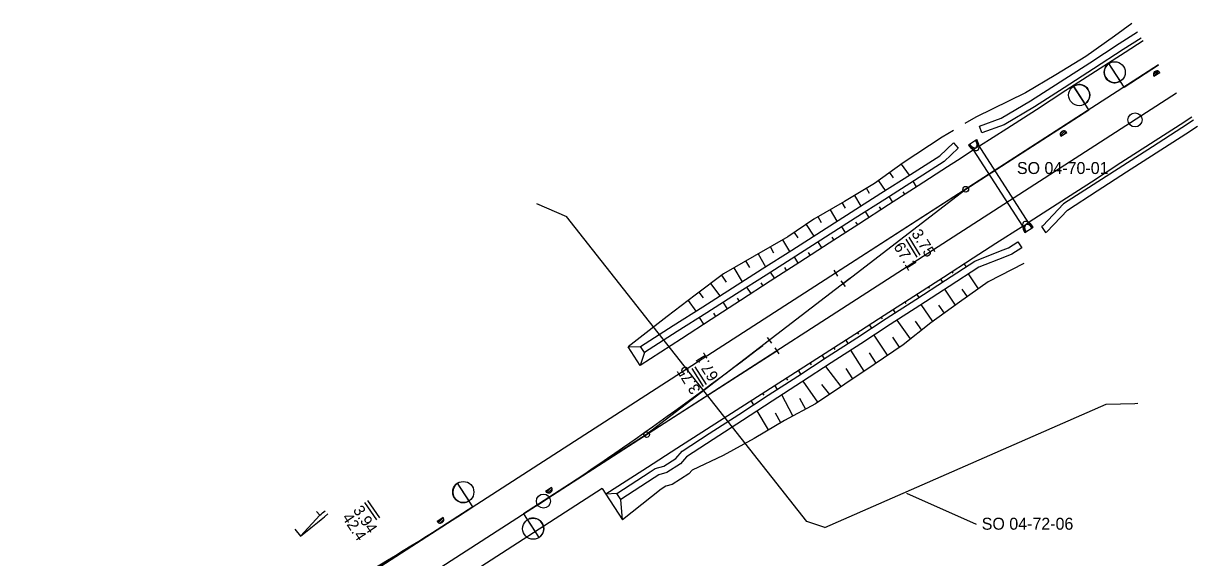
# Model space of a CAD drawing. Extents: x -723225 to -722352, y -1040354 to -1039760.
# Drawn here: x -722561.5 to -722394.6, y -1039969.1 to -1039893.3 of the extents above; entities that cross this region are included whole.
import ezdxf

# ---------------------------------------------------------------- set-up
doc = ezdxf.new("R2010")
doc.units = 0
for name, color, linetype in [('_PS_SO_číslo', 7, 'Continuous'), ('SO 03_01_01', 7, 'Continuous'), ('SO 04_70_01', 7, 'Continuous'), ('SO 04_72_06', 7, 'Continuous')]:
    doc.layers.add(name, color=color, linetype=linetype)

msp = doc.modelspace()

# ---------------------------------------------------------------- linework, layer by layer
at = {"layer": '_PS_SO_číslo'}
msp.add_line((-722435.98, -1039960.01), (-722426.1, -1039964.39), dxfattribs=at)
at = {"layer": 'SO 03_01_01'}
for p, q in [((-722400.19, -1039899.16), (-722541.14, -1039990)), ((-722400.91, -1039900.51), (-722400.39, -1039899.99)), ((-722400.85, -1039900.73), (-722400.17, -1039900.05)), ((-722400.17, -1039900.34), (-722400.02, -1039900.18)), ((-722400.83, -1039900.76), (-722400.83, -1039900.76)), ((-722397.63, -1039903.16), (-722561.45, -1040008.75)), ((-722414.14, -1039908.93), (-722413.74, -1039908.53)), ((-722414.12, -1039909.19), (-722413.48, -1039908.55)), ((-722413.7, -1039909.06), (-722413.3, -1039908.66)), ((-722413.23, -1039908.75), (-722413.23, -1039908.75)), ((-722436.74, -1039913.27), (-722435.61, -1039914.83)), ((-722437.83, -1039915.17), (-722438.36, -1039914.44)), ((-722441.23, -1039917.4), (-722441.67, -1039916.68)), ((-722439.98, -1039915.61), (-722439.03, -1039917.01)), ((-722434.55, -1039916.47), (-722435.06, -1039915.69)), ((-722443.39, -1039917.7), (-722442.49, -1039919.21)), ((-722437.91, -1039918.64), (-722438.43, -1039917.84)), ((-722436.49, -1039917.16), (-722436.23, -1039917.56)), ((-722446.84, -1039919.73), (-722445.88, -1039921.37)), ((-722444.65, -1039919.5), (-722445.11, -1039918.72)), ((-722441.28, -1039920.81), (-722441.8, -1039919.99)), ((-722439.86, -1039919.32), (-722439.6, -1039919.72)), ((-722450.24, -1039921.82), (-722449.16, -1039923.46)), ((-722448.05, -1039921.58), (-722448.56, -1039920.74)), ((-722443.22, -1039921.48), (-722442.96, -1039921.89)), ((-722451.38, -1039923.74), (-722451.9, -1039922.94)), ((-722446.59, -1039923.63), (-722446.32, -1039924.06)), ((-722444.64, -1039922.97), (-722445.18, -1039922.14)), ((-722454.83, -1039925.88), (-722455.33, -1039925)), ((-722453.59, -1039924.01), (-722452.6, -1039925.66)), ((-722448, -1039925.14), (-722448.55, -1039924.29)), ((-722458.24, -1039927.94), (-722458.8, -1039926.99)), ((-722457.07, -1039925.99), (-722456.01, -1039927.83)), ((-722451.36, -1039927.31), (-722451.92, -1039926.44)), ((-722449.96, -1039925.79), (-722449.68, -1039926.22)), ((-722460.52, -1039928), (-722459.36, -1039929.96)), ((-722454.72, -1039929.48), (-722455.3, -1039928.59)), ((-722453.33, -1039927.95), (-722453.04, -1039928.39)), ((-722446.33, -1039928.31), (-722445.79, -1039929.15)), ((-722429.34, -1039928.73), (-722429.48, -1039928.52)), ((-722427.8, -1039927.44), (-722427.53, -1039927.85)), ((-722463.83, -1039930.23), (-722462.53, -1039931.98)), ((-722461.58, -1039930), (-722462.23, -1039929.03)), ((-722456.69, -1039930.11), (-722456.4, -1039930.56)), ((-722444.06, -1039929.49), (-722456.43, -1039939)), ((-722445.31, -1039929.82), (-722444.7, -1039930.62)), ((-722431.16, -1039929.61), (-722430.89, -1039930.02)), ((-722425.75, -1039930.96), (-722427.17, -1039928.83)), ((-722464.83, -1039932.24), (-722465.44, -1039931.43)), ((-722458.08, -1039931.65), (-722458.67, -1039930.74)), ((-722434.52, -1039931.77), (-722434.25, -1039932.2)), ((-722432.7, -1039930.9), (-722432.84, -1039930.69)), ((-722429.02, -1039933.27), (-722430.52, -1039931.01)), ((-722428.11, -1039931.01), (-722427.38, -1039932.11)), ((-722467.03, -1039932.64), (-722465.9, -1039934.12)), ((-722461.44, -1039933.83), (-722462.05, -1039932.88)), ((-722460.06, -1039932.28), (-722459.76, -1039932.74)), ((-722436.06, -1039933.07), (-722436.2, -1039932.86)), ((-722432.26, -1039935.6), (-722433.92, -1039933.21)), ((-722431.42, -1039933.27), (-722430.64, -1039934.44)), ((-722464.79, -1039936), (-722465.42, -1039935.03)), ((-722463.43, -1039934.44), (-722463.12, -1039934.91)), ((-722439.42, -1039935.24), (-722439.56, -1039935.02)), ((-722437.88, -1039933.94), (-722437.6, -1039934.38)), ((-722441.24, -1039936.11), (-722440.96, -1039936.55)), ((-722435.41, -1039938.06), (-722437.31, -1039935.41)), ((-722434.74, -1039935.58), (-722433.84, -1039936.83)), ((-722455.78, -1039937.87), (-722455.17, -1039938.67)), ((-722444.61, -1039938.27), (-722444.31, -1039938.73)), ((-722442.78, -1039937.42), (-722442.93, -1039937.19)), ((-722438.67, -1039940.41), (-722440.58, -1039937.53)), ((-722437.99, -1039937.85), (-722437.02, -1039939.27)), ((-722454.69, -1039939.34), (-722454.15, -1039940.18)), ((-722446.14, -1039939.59), (-722446.29, -1039939.36)), ((-722441.99, -1039942.67), (-722443.88, -1039939.67)), ((-722441.28, -1039940.07), (-722440.33, -1039941.55)), ((-722449.5, -1039941.76), (-722449.65, -1039941.52)), ((-722447.97, -1039940.44), (-722447.67, -1039940.91)), ((-722445.26, -1039944.85), (-722447.45, -1039941.99)), ((-722452.86, -1039943.93), (-722453.02, -1039943.68)), ((-722451.34, -1039942.6), (-722451.03, -1039943.09)), ((-722444.63, -1039942.28), (-722443.64, -1039943.77)), ((-722454.71, -1039944.76), (-722454.38, -1039945.26)), ((-722448.6, -1039947.09), (-722450.69, -1039944.09)), ((-722448.08, -1039944.56), (-722446.91, -1039945.96)), ((-722458.07, -1039946.91), (-722457.74, -1039947.44)), ((-722456.22, -1039946.09), (-722456.39, -1039945.84)), ((-722452.13, -1039949.02), (-722453.7, -1039946.04)), ((-722451.21, -1039946.52), (-722450.36, -1039948.07)), ((-722455.58, -1039951.01), (-722457.19, -1039948.31)), ((-722454.66, -1039948.6), (-722453.87, -1039949.98)), ((-722479.22, -1039959.32), (-722526.95, -1039990.08)), ((-722487.26, -1039959.74), (-722487.26, -1039959.74)), ((-722487.14, -1039959.87), (-722486.56, -1039959.29)), ((-722486.94, -1039959.96), (-722486.35, -1039959.36)), ((-722486.63, -1039959.93), (-722486.38, -1039959.67)), ((-722519.35, -1039963.13), (-722522.11, -1039966.11)), ((-722519.8, -1039962.59), (-722519.35, -1039963.13)), ((-722502.48, -1039964.18), (-722501.8, -1039963.5)), ((-722501.82, -1039963.47), (-722501.82, -1039963.47)), ((-722522.91, -1039965.09), (-722522.11, -1039966.11)), ((-722502.64, -1039964.05), (-722502.49, -1039963.91)), ((-722502.26, -1039964.25), (-722501.74, -1039963.72))]:
    msp.add_line(p, q, dxfattribs=at)
for points in [[(-722403.95, -1039893.26), (-722406.43, -1039895.05), (-722410.51, -1039897.95), (-722414.78, -1039900.56), (-722419.08, -1039903.12), (-722426.16, -1039906.58)], [(-722402.63, -1039895.33), (-722405.19, -1039896.98), (-722409.4, -1039899.69), (-722413.6, -1039902.4), (-722417.8, -1039905.1), (-722422.11, -1039907.64), (-722425.3, -1039908.79), (-722425.62, -1039907.85), (-722422.55, -1039906.72), (-722418.36, -1039904.24), (-722414.15, -1039901.53), (-722409.95, -1039898.83), (-722405.75, -1039896.12), (-722403.18, -1039894.46)], [(-722402.37, -1039895.73), (-722404.93, -1039897.38), (-722409.14, -1039900.09), (-722413.34, -1039902.8), (-722417.54, -1039905.51), (-722421.74, -1039908.22), (-722425.6, -1039910.7)], [(-722405.59, -1039901.45), (-722407.22, -1039898.93)], [(-722405.05, -1039902.29), (-722407.22, -1039898.93)], [(-722400.19, -1039899.16), (-722405.05, -1039902.29), (-722400.19, -1039899.16)], [(-722399.99, -1039900.22), (-722399.99, -1039900.22), (-722400.83, -1039900.76), (-722400.83, -1039900.76)], [(-722400.83, -1039900.76), (-722399.99, -1039900.22), (-722399.99, -1039900.22)], [(-722400.83, -1039900.76), (-722400.83, -1039900.76), (-722400.83, -1039900.76)], [(-722412.26, -1039902.18), (-722410.63, -1039904.7)], [(-722410.09, -1039905.54), (-722412.26, -1039902.18)], [(-722445.01, -1039930.22), (-722427.57, -1039916.81), (-722410.09, -1039905.54), (-722427.57, -1039916.81), (-722446.06, -1039928.73)], [(-722426.16, -1039906.58), (-722427.68, -1039907.48)], [(-722395.45, -1039906.59), (-722397.11, -1039907.67), (-722401.32, -1039910.37), (-722405.52, -1039913.08), (-722409.72, -1039915.79), (-722413.93, -1039918.5), (-722418.57, -1039921.49)], [(-722429.32, -1039908.46), (-722430.9, -1039909.4)], [(-722395.19, -1039907), (-722396.85, -1039908.07), (-722401.06, -1039910.78), (-722405.26, -1039913.49), (-722409.46, -1039916.2), (-722413.67, -1039918.9), (-722416.61, -1039921.99), (-722416.8, -1039922.11), (-722416.24, -1039922.97), (-722416.05, -1039922.85), (-722413.11, -1039919.77), (-722408.91, -1039917.06), (-722404.71, -1039914.35), (-722400.5, -1039911.64), (-722396.3, -1039908.93), (-722394.64, -1039907.86)], [(-722430.9, -1039909.4), (-722436.46, -1039913.07), (-722440.52, -1039916), (-722444.82, -1039918.55), (-722449.14, -1039921.08), (-722452.84, -1039923.58), (-722457.65, -1039926.32), (-722461.99, -1039928.85), (-722466, -1039931.85), (-722469.98, -1039934.9), (-722475.52, -1039939.22)], [(-722473.79, -1039939.15), (-722469.15, -1039936.19), (-722464.93, -1039933.51), (-722460.71, -1039930.82), (-722456.49, -1039928.13), (-722452.28, -1039925.45), (-722448.06, -1039922.76), (-722443.84, -1039920.07), (-722439.63, -1039917.39), (-722435.41, -1039914.7), (-722431.26, -1039912.05), (-722429.32, -1039910.22), (-722428.64, -1039910.96), (-722430.64, -1039912.87), (-722434.86, -1039915.56), (-722439.07, -1039918.25), (-722443.29, -1039920.93), (-722447.51, -1039923.62), (-722451.72, -1039926.31), (-722455.94, -1039929), (-722460.16, -1039931.68), (-722464.37, -1039934.37), (-722468.59, -1039937.05), (-722473.23, -1039940.01)], [(-722414.07, -1039909.29), (-722414.07, -1039909.29), (-722413.23, -1039908.75), (-722413.23, -1039908.75)], [(-722414.07, -1039909.29), (-722414.07, -1039909.29), (-722413.23, -1039908.75)], [(-722413.23, -1039908.75), (-722413.23, -1039908.75), (-722413.23, -1039908.75)], [(-722426.5, -1039911.28), (-722428.75, -1039912.73)], [(-722428.75, -1039912.73), (-722430.15, -1039913.63), (-722434.35, -1039916.34), (-722438.55, -1039919.05), (-722442.76, -1039921.76), (-722446.96, -1039924.47), (-722451.16, -1039927.18), (-722455.36, -1039929.89), (-722459.56, -1039932.61), (-722463.75, -1039935.33), (-722467.95, -1039938.05), (-722473.83, -1039941.85)], [(-722434.05, -1039926.19), (-722435.63, -1039923.64)], [(-722419.57, -1039922.14), (-722423.29, -1039924.54)], [(-722423.29, -1039924.54), (-722426.53, -1039926.63), (-722430.74, -1039929.34), (-722434.94, -1039932.04), (-722439.14, -1039934.75), (-722443.34, -1039937.46), (-722447.55, -1039940.17), (-722451.76, -1039942.87), (-722455.97, -1039945.56), (-722460.18, -1039948.26), (-722464.39, -1039950.96), (-722468.6, -1039953.66), (-722472.8, -1039956.36), (-722477.01, -1039959.06), (-722478.7, -1039960.13)], [(-722477.14, -1039960.04), (-722472.41, -1039956.97), (-722471.68, -1039956.5), (-722470.47, -1039956.15), (-722468.78, -1039955.08), (-722467.85, -1039954.01), (-722464.02, -1039951.52), (-722459.83, -1039948.8), (-722455.64, -1039946.08), (-722451.44, -1039943.36), (-722447.25, -1039940.63), (-722443.05, -1039937.91), (-722438.86, -1039935.19), (-722434.66, -1039932.47), (-722430.47, -1039929.75), (-722426.27, -1039927.03), (-722422.62, -1039925.58), (-722421.52, -1039925.15), (-722420.16, -1039924.27), (-722419.61, -1039925.14), (-722421.02, -1039926.05), (-722422.05, -1039926.46), (-722425.72, -1039927.89), (-722429.91, -1039930.61), (-722434.11, -1039933.33), (-722438.3, -1039936.05), (-722442.5, -1039938.77), (-722446.69, -1039941.49), (-722450.89, -1039944.22), (-722455.08, -1039946.94), (-722459.28, -1039949.66), (-722463.47, -1039952.38), (-722467.25, -1039954.84), (-722468.12, -1039955.85), (-722470.05, -1039957.08), (-722471.19, -1039957.4), (-722471.86, -1039957.83), (-722476.59, -1039960.9)], [(-722434.47, -1039926.46), (-722436.05, -1039923.91)], [(-722419.32, -1039927.36), (-722424.37, -1039929.98), (-722428.46, -1039932.87), (-722432.52, -1039935.79), (-722436.47, -1039938.9), (-722440.59, -1039941.73), (-722444.75, -1039944.51), (-722448.9, -1039947.3), (-722453.33, -1039949.66), (-722457.62, -1039952.23), (-722462.02, -1039954.63), (-722466.46, -1039956.72), (-722466.91, -1039957.24), (-722469.3, -1039958.76), (-722470.19, -1039959.01), (-722470.84, -1039959.41), (-722476.33, -1039963.81)], [(-722455.47, -1039938.27), (-722472.91, -1039951.68), (-722490.39, -1039962.95), (-722472.91, -1039951.68), (-722454.42, -1039939.76)], [(-722473.23, -1039940.01), (-722473.83, -1039941.85), (-722475.52, -1039939.22), (-722473.79, -1039939.15)], [(-722473.23, -1039940.01), (-722473.79, -1039939.15)], [(-722464.85, -1039944.85), (-722466.44, -1039942.3)], [(-722464.43, -1039944.58), (-722466.01, -1039942.04)], [(-722498.14, -1039961.1), (-722499.77, -1039958.58)], [(-722497.6, -1039961.94), (-722499.77, -1039958.58)], [(-722486.42, -1039959.2), (-722486.42, -1039959.2), (-722487.26, -1039959.74), (-722487.26, -1039959.74)], [(-722486.42, -1039959.2), (-722486.42, -1039959.2), (-722487.26, -1039959.74)], [(-722487.26, -1039959.74), (-722487.26, -1039959.74), (-722487.26, -1039959.74)], [(-722479.22, -1039959.32), (-722478.7, -1039960.13)], [(-722476.59, -1039960.9), (-722477.14, -1039960.04), (-722478.7, -1039960.13), (-722476.33, -1039963.81), (-722476.59, -1039960.9)], [(-722534.5, -1039983.55), (-722515.08, -1039973.21), (-722497.6, -1039961.94), (-722515.08, -1039973.21), (-722533.57, -1039985.13)], [(-722511.24, -1039963.77), (-722512.96, -1039961.31)], [(-722510.83, -1039963.48), (-722512.54, -1039961.02)], [(-722502.66, -1039964.02), (-722502.66, -1039964.02), (-722501.82, -1039963.47), (-722501.82, -1039963.47)], [(-722501.82, -1039963.47), (-722502.66, -1039964.02), (-722502.66, -1039964.02)], [(-722501.82, -1039963.47), (-722501.82, -1039963.47), (-722501.82, -1039963.47)], [(-722490.39, -1039962.95), (-722488.22, -1039966.31)], [(-722489.85, -1039963.79), (-722488.22, -1039966.31)]]:
    msp.add_lwpolyline(points, dxfattribs=at)
for centre, radius in [((-722406.4, -1039900.19), 1.5), ((-722411.45, -1039903.44), 1.5), ((-722403.52, -1039906.96), 1), ((-722427.57, -1039916.81), 0.4), ((-722472.91, -1039951.68), 0.4), ((-722498.96, -1039959.84), 1.5), ((-722487.57, -1039961.13), 1), ((-722489.04, -1039965.05), 1.5)]:
    msp.add_circle(centre, radius, dxfattribs=at)
for centre, radius, start, end in [((-722406.4, -1039900.19), 1.5, 122.8026, 180), ((-722406.4, -1039900.19), 1.5, 180, 302.8026), ((-722134.18, -1040322.56), 500, 122.1398, 122.8026), ((-722400.41, -1039900.49), 0.5, 32.5047, 213.1017), ((-722400.41, -1039900.49), 0.5, 32.5047, 213.1005), ((-722411.45, -1039903.44), 1.5, 0, 122.8026), ((-722400.41, -1039900.49), 0.5, 213.1005, 213.1017), ((-722411.45, -1039903.44), 1.5, 302.8026, 0), ((-722413.65, -1039909.02), 0.5, 32.5035, 213.1005), ((-722413.65, -1039909.02), 0.5, 32.5046, 213.1005), ((-722413.65, -1039909.02), 0.5, 32.5035, 32.5046), ((-722761.26, -1039542.68), 500, 302.8026, 307.5662), ((-722498.96, -1039959.84), 1.5, 122.8026, 180), ((-722498.96, -1039959.84), 1.5, 180, 302.8026), ((-722486.83, -1039959.47), 0.5, 212.5035, 33.1005), ((-722486.83, -1039959.47), 0.5, 212.5046, 33.1005), ((-722486.83, -1039959.47), 0.5, 212.5035, 212.5046), ((-722768.48, -1039541.67), 500, 298.039, 302.8026), ((-722638.5, -1039818.09), 188.3, 308.1773, 309.707), ((-722638.5, -1039818.09), 187.7, 309.4027, 309.708), ((-722502.24, -1039963.75), 0.5, 212.5047, 33.1017), ((-722502.24, -1039963.75), 0.5, 212.5047, 33.1005), ((-722502.24, -1039963.75), 0.5, 33.1005, 33.1017), ((-722489.04, -1039965.05), 1.5, 0, 122.8026), ((-722489.04, -1039965.05), 1.5, 302.8026, 360)]:
    msp.add_arc(centre, radius, start, end, dxfattribs=at)
at = {"layer": 'SO 04_70_01'}
for p, q in [((-722427.18, -1039910.5), (-722426.02, -1039909.76)), ((-722418.16, -1039922.3), (-722426.18, -1039909.86)), ((-722427.03, -1039910.41), (-722419.01, -1039922.85)), ((-722426.37, -1039911.05), (-722425.86, -1039910.72)), ((-722419.33, -1039921.99), (-722418.81, -1039921.65)), ((-722419.17, -1039922.94), (-722418.01, -1039922.2))]:
    msp.add_line(p, q, dxfattribs=at)
for centre, major_axis, ratio, start_param, end_param in [((-722426.6, -1039910.13), (-0.72, 1.12), 0.519656, 1.570798, 4.712389), ((-722426.6, -1039910.13), (-0.487, 0.756), 0.555679, 1.570796, 4.712389), ((-722426.6, -1039910.13), (-0.544, 0.845), 0.686581, 3.603192, 4.712389), ((-722426.6, -1039910.13), (-0.544, 0.845), 0.686581, 1.570796, 2.679993), ((-722418.59, -1039922.57), (0.72, -1.12), 0.519656, 1.570796, 4.712387), ((-722418.59, -1039922.57), (0.544, -0.845), 0.686581, 3.615245, 4.712389), ((-722418.59, -1039922.57), (0.45, -0.698), 0.602529, 1.570796, 4.712389), ((-722418.59, -1039922.57), (0.544, -0.845), 0.686581, 1.570796, 2.66794)]:
    msp.add_ellipse(centre, major_axis=major_axis, ratio=ratio, start_param=start_param, end_param=end_param, dxfattribs=at)
at = {"layer": 'SO 04_72_06'}
for points in [[(-722488.55, -1039918.85), (-722484.29, -1039920.7)], [(-722447.61, -1039964.89), (-722450.15, -1039964.03), (-722484.29, -1039920.7)], [(-722447.61, -1039964.89), (-722407.61, -1039947.37), (-722403.55, -1039947.28), (-722403.12, -1039947.23)]]:
    msp.add_lwpolyline(points, dxfattribs=at)

# ---------------------------------------------------------------- texts
at = {"layer": '_PS_SO_číslo'}
for s, p in [('SO 04-70-01', (-722420.3, -1039914.65)), ('SO 04-72-06', (-722425.3, -1039965.19))]:
    msp.add_text(s, height=1.7, dxfattribs=at).set_placement(p)
at = {"layer": 'SO 03_01_01'}
for s, rotation, p in [('3.75', 301.8677, (-722435.35, -1039923.1)), ('67.1', 301.8677, (-722437.89, -1039924.96)), ('67.1', 121.7727, (-722462.62, -1039943.45)), ('3.75', 121.7727, (-722465.17, -1039945.31)), ('3.94', 303.4198, (-722514.7, -1039962.4)), ('42.4', 303.4198, (-722516.25, -1039963.46))]:
    msp.add_text(s, height=1.6, rotation=rotation, dxfattribs=at).set_placement(p)

doc.saveas('drawing.dxf')
